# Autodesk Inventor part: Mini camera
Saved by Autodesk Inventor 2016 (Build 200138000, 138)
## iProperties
Created: 2013-08
Part Number: Mini camera
Material: Générique
Document SubType Name: Modeling
Designer: hilarion
Density: 1 g/cm^3
Appearance: Par défaut
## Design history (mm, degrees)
node "Mini camera1"
node "Mini camera"
node "Base1"
